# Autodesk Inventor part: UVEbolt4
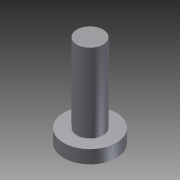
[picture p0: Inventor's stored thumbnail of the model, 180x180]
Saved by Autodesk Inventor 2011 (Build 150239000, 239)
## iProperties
Created: 2014-12
Part Number: UVEbolt4
Document SubType Name: Modeling
Designer: Evgeny
Density: 1 g/cm^3
Mass: 0.251327 g
Surface Area: 3.01593 cm^2
Volume: 0.251327 cm^3
Author: Evgeny
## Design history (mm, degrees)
sketch "Эскиз1"
  geometry: C1 r 2 at (0, 0); C2 r 4 at (0, 0); 1 further point
  constraints: 2 centre point, 2 coincident
  dimensions: "d0" = 4 diameter of C1; "d1" = 8 diameter of C2
extrude "Выдавливание1" new body sketch "Эскиз1" distance "d2" = 12; taper "d3" = 0 deg
extrude "Выдавливание2" join sketch "Эскиз1" distance "d4" = 2; taper "d5" = 0 deg
node "Твердое тело1"
